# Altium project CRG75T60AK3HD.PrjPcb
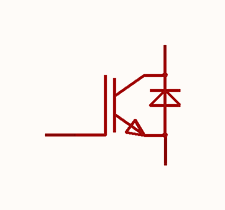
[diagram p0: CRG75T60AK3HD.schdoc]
1 sheet, 1 parts. Net scope: global (net labels, ports and power ports of the same name join across sheets).

## Sheet CRG75T60AK3HD.schdoc
size 127 x 101 mm

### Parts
Q?  crg75t60ak3hd  [TO-247-3_L15.8-W5.0-P5.44-L]  (value not drawn)

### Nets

Not connected (* = marked no-connect by the designer): Q? 1(G) 2(C) 3(E)

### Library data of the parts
Q? = crg75t60ak3hd: IGBT类型:FS(场截止);耗散功率(Pd):390W;集射极击穿电压(Vces):600V;集电极电流(Ic):150A;; Manufacturer: CRMICRO(华润微); AddInBom: yes; ModelId: 2dc33f6e48bd44aa838c2b9e2b85eb16; ModelTransform: 622.04631,185.078,0,0,0,0,-0.003,13.778,-196.85; Pd - Power Dissipation: 390W; Collector-Emitter Breakdown Voltage (Vces): 600V; Current - Collector(Ic): 150A; Current - Collector Pulsed (Icm): 300A; Vce Saturation(VCE(sat)): 2.4V@75A,15V; Gate-Emitter Threshold Voltage (Vge(th)@Ic): 4V@250uA; Gate Charge(Qg): 433nC@15V; Input Capacitance(Cies): 11.67nF; Output Capacitance(Coes): 268pF; Reverse Transfer Capacitance (Cres): 180pF; Td(on): 96.5ns; Td(off): 308.4ns; Turn-On Energy (Eon): 4.6mJ; Switching Energy(Eoff): 2.1mJ; Reverse Recovery Time(trr): 65ns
